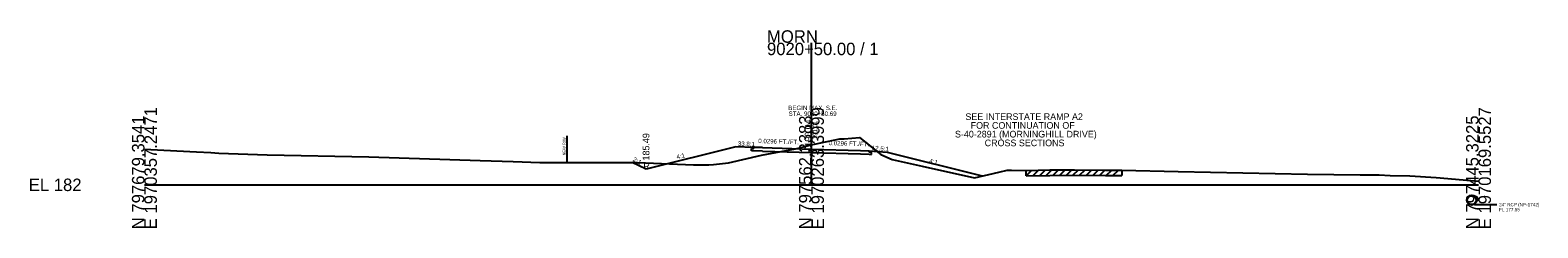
# Model space of a CAD drawing. Extents: x -26 to 2313, y -1511 to 5559.
# Drawn here: x 1974.3 to 2313.3, y 490.3 to 534.8 of the extents above; entities that cross this region are included whole.
import ezdxf

# ---------------------------------------------------------------- set-up
doc = ezdxf.new("R2010")
doc.units = 0
for name, color, linetype in [('RD_GPK_XS_Cell', 7, 'Continuous'), ('RD_XS_Base', 7, 'Continuous'), ('RD_XS_EarthShd', 7, 'Continuous'), ('RD_XS_ExGround', 7, 'Continuous'), ('RD_XS_ExPaveRet', 7, 'Continuous'), ('RD_XS_Misc_Line', 7, 'Continuous'), ('RD_XS_NewRW', 7, 'Continuous'), ('RD_XS_Pave', 7, 'Continuous'), ('RD_XS_PaveShd', 7, 'Continuous'), ('RD_XS_Pipe', 7, 'Continuous'), ('RD_XS_TieSlope', 7, 'Continuous'), ('RD_XS_TX_Elev_EX', 7, 'Continuous'), ('RD_XS_TX_Elev_PR', 7, 'Continuous'), ('RD_XS_TX_Misc', 7, 'Continuous'), ('RD_XS_TX_MkPT', 7, 'Continuous'), ('RD_XS_TX_Notes', 7, 'Continuous'), ('RD_XS_TX_ShdSlope', 7, 'Continuous'), ('RD_XS_TX_Slope', 7, 'Continuous')]:
    doc.layers.add(name, color=color, linetype=linetype)

msp = doc.modelspace()

# ---------------------------------------------------------------- linework, layer by layer
at = {"layer": 'RD_GPK_XS_Cell'}
for p, q in [((2150, 500), (2150, 531.99)), ((2000, 500), (2150, 500)), ((2150, 500), (2300, 500))]:
    msp.add_line(p, q, dxfattribs=at)
at = {"layer": 'RD_XS_Base'}
for p, q in [((2136.5, 508.14), (2137, 508.13)), ((2136.5, 507.66), (2136.5, 508.14)), ((2139, 507.59), (2136.5, 507.66)), ((2137, 508.13), (2137, 508.43)), ((2161, 506.94), (2163, 506.88)), ((2163, 507.36), (2163, 507.66)), ((2163.5, 507.34), (2163, 507.36)), ((2163, 506.88), (2163.5, 506.86)), ((2163.5, 506.86), (2163.5, 507.34))]:
    msp.add_line(p, q, dxfattribs=at)
at = {"layer": 'RD_XS_EarthShd'}
for p, q in [((2137, 508.43), (2133, 508.54)), ((2163, 507.66), (2167, 507.34))]:
    msp.add_line(p, q, dxfattribs=at)
at = {"layer": 'RD_XS_ExGround'}
msp.add_lwpolyline([(2000, 508), (2007.32, 507.63), (2011.7, 507.44), (2014.93, 507.24), (2016.72, 507.11), (2027.57, 506.77), (2050.45, 506.33), (2075.51, 505.49), (2082.94, 505.27), (2088.9, 505.06), (2110.87, 505.04), (2123.46, 504.49), (2126.94, 504.5), (2127.97, 504.56), (2131.36, 504.93), (2138.8, 506.68), (2146.4, 508.11), (2150, 509.01), (2150.67, 509.18), (2156.37, 510.33), (2157.37, 510.33), (2160.83, 510.66), (2165.57, 506.81), (2168.16, 505.68), (2174.86, 504.21), (2186.66, 501.61), (2192.14, 502.87), (2194.01, 503.28), (2194.98, 503.28), (2198.25, 503.26), (2203.58, 503.34), (2209.12, 503.41), (2216.15, 503.33), (2219.79, 503.33), (2232.49, 502.97), (2261.57, 502.43), (2273.41, 502.24), (2277.69, 502.23), (2280.16, 502.1), (2284.53, 501.99), (2290.49, 501.66), (2300, 500.8)], dxfattribs=at)
at = {"layer": 'RD_XS_ExPaveRet'}
for p, q in [((2198.25, 502.01), (2198.25, 503.26)), ((2198.25, 502.01), (2203.58, 502.09)), ((2203.58, 502.09), (2209.12, 502.16)), ((2209.12, 502.16), (2216.15, 502.08)), ((2216.15, 502.08), (2219.79, 502.08)), ((2219.79, 503.33), (2219.79, 502.08))]:
    msp.add_line(p, q, dxfattribs=at)
at = {"layer": 'RD_XS_Misc_Line'}
for p, q in [((2198.25, 502.01), (2199.52, 503.28)), ((2199.75, 502.03), (2201.03, 503.3)), ((2201.26, 502.06), (2202.53, 503.33)), ((2202.76, 502.08), (2204.03, 503.35)), ((2204.26, 502.1), (2205.53, 503.37)), ((2205.76, 502.12), (2207.03, 503.38)), ((2207.27, 502.13), (2208.53, 503.4)), ((2208.77, 502.15), (2210.02, 503.4)), ((2210.27, 502.14), (2211.51, 503.38)), ((2211.77, 502.13), (2213.01, 503.37)), ((2213.28, 502.11), (2214.52, 503.35)), ((2214.78, 502.1), (2216.02, 503.34)), ((2216.28, 502.08), (2217.53, 503.33)), ((2217.78, 502.08), (2219.03, 503.33))]:
    msp.add_line(p, q, dxfattribs=at)
at = {"layer": 'RD_XS_NewRW'}
msp.add_line((2095, 511.05), (2095, 505.05), dxfattribs=at)
at = {"layer": 'RD_XS_Pave'}
for p, q in [((2139, 508.37), (2150, 508.04)), ((2139, 507.59), (2150, 507.26)), ((2150, 508.04), (2161, 507.72)), ((2150, 507.26), (2161, 506.94))]:
    msp.add_line(p, q, dxfattribs=at)
at = {"layer": 'RD_XS_PaveShd'}
for p, q in [((2139, 508.37), (2137, 508.43)), ((2161, 507.72), (2163, 507.66))]:
    msp.add_line(p, q, dxfattribs=at)
at = {"layer": 'RD_XS_Pipe'}
msp.add_line((2299.13, 495.55), (2304.13, 495.55), dxfattribs=at)
for radius in [1.1, 1]:
    msp.add_circle((2298.46, 496.55), radius, dxfattribs=at)
at = {"layer": 'RD_XS_TieSlope'}
for p, q in [((2133, 508.54), (2112.8, 503.49)), ((2167, 507.34), (2188.35, 502)), ((2112.8, 503.49), (2109.71, 505.04))]:
    msp.add_line(p, q, dxfattribs=at)

# ---------------------------------------------------------------- texts
at = {"layer": 'RD_GPK_XS_Cell'}
for s, p in [('MORN', (2140, 531.99)), ('9020+50.00 / 1', (2140, 529.19)), ('EL 182', (1974, 498.6))]:
    msp.add_text(s, height=2.8, dxfattribs=at).set_placement(p)
for s, p in [('N 797679.3541', (2000, 490)), ('E 1970357.2471', (2002.8, 490)), ('N 797562.3383', (2150, 490)), ('E 1970263.3999', (2152.8, 490)), ('N 797445.3225', (2300, 490)), ('E 1970169.5527', (2302.8, 490))]:
    msp.add_text(s, height=2.8, rotation=90, dxfattribs=at).set_placement(p)
at = {"layer": 'RD_XS_NewRW'}
msp.add_text('NEW R/W ', height=0.65, rotation=90, dxfattribs=at).set_placement((2094.73, 506.61))
at = {"layer": 'RD_XS_Pipe'}
for s, p in [('24" RCP (NP-1742)', (2304.63, 495.17)), ('FL 177.55', (2304.63, 494.05))]:
    msp.add_text(s, height=0.75, dxfattribs=at).set_placement(p)
at = {"layer": 'RD_XS_TX_Elev_EX'}
msp.add_text('191.01', height=1, rotation=90, dxfattribs=at).set_placement((2151.29, 510.24))
at = {"layer": 'RD_XS_TX_Elev_PR'}
msp.add_text(' 190.04', height=1.5, rotation=90, dxfattribs=at).set_placement((2150, 508.04))
at = {"layer": 'RD_XS_TX_Misc'}
msp.add_text('185.49', height=1.5, rotation=90, dxfattribs=at).set_placement((2113.55, 505.49))
at = {"layer": 'RD_XS_TX_MkPT'}
msp.add_text('R', height=1.5, dxfattribs=at).set_placement((2112.21, 503.49))
at = {"layer": 'RD_XS_TX_Notes'}
for s, height, p in [('BEGIN MAX. S.E. ', 1, (2144.79, 516.82)), ('STA. 9020+50.69', 1, (2144.87, 515.51)), ('SEE INTERSTATE RAMP A2', 1.5, (2184.62, 514.59)), ('S-40-2891 (MORNINGHILL DRIVE)', 1.5, (2182.27, 510.66)), ('FOR CONTINUATION OF', 1.5, (2185.8, 512.62)), ('CROSS SECTIONS', 1.5, (2188.95, 508.69))]:
    msp.add_text(s, height=height, dxfattribs=at).set_placement(p)
at = {"layer": 'RD_XS_TX_ShdSlope'}
for s, rotation, p in [('33.8:1', 358.3051, (2133.43, 508.78)), ('12.5:1', 355.4261, (2163.54, 507.86))]:
    msp.add_text(s, height=1, rotation=rotation, dxfattribs=at).set_placement(p)
at = {"layer": 'RD_XS_TX_Slope'}
for s, rotation, p in [('0.0296 FT./FT.', 358.3051, (2138.03, 509.4)), ('0.0296 FT./FT.', 358.3051, (2153.84, 508.93)), ('2:1', 333.4349, (2109.75, 505.4)), ('4:1', 14.0362, (2119.77, 505.75)), ('4:1', 345.9638, (2176.4, 504.99))]:
    msp.add_text(s, height=1, rotation=rotation, dxfattribs=at).set_placement(p)

doc.saveas('drawing.dxf')
